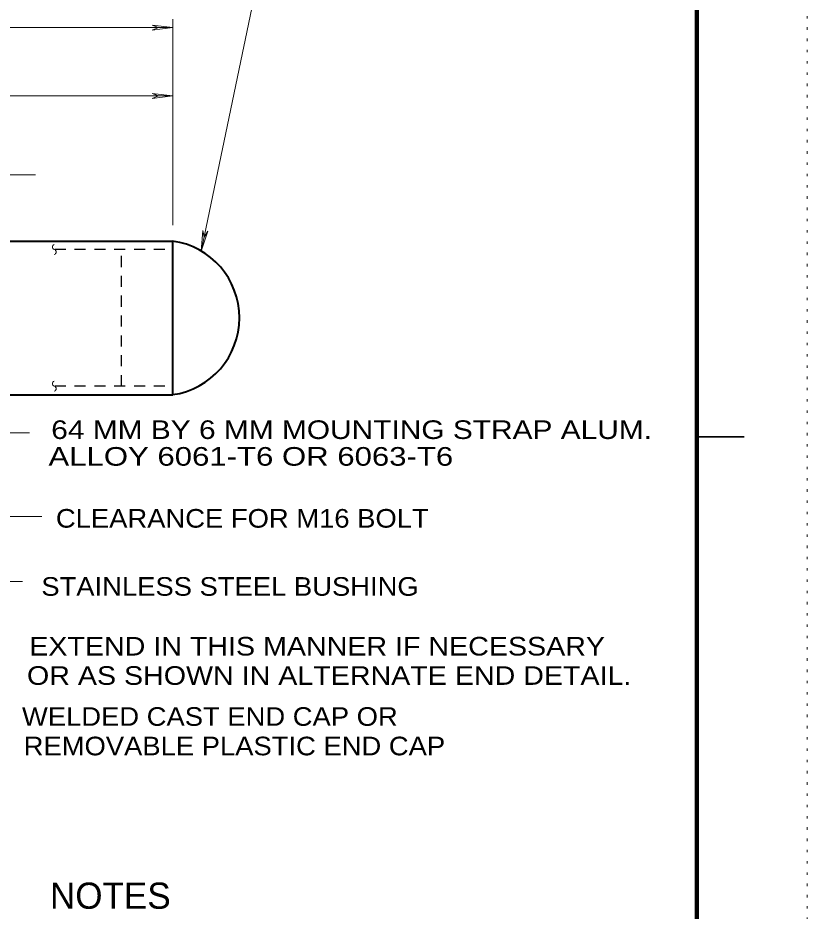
# Model space of a CAD drawing. Extents: x 312583 to 312854, y 144419 to 144597.
# Drawn here: x 312821.27 to 312853.5, y 144484.26 to 144520.73 of the extents above; entities that cross this region are included whole.
import ezdxf
from ezdxf.enums import TextEntityAlignment as Align

# ---------------------------------------------------------------- set-up
doc = ezdxf.new("R2010")
doc.units = 0
doc.header["$LTSCALE"] = 0.3
doc.linetypes.add('DOTTED', pattern=[1.5, 0.3, -1.2])
doc.linetypes.add('SHORT_DASHED', pattern=[2.7, 1.5, -1.2])
for name, color, linetype, lineweight in [('1', 7, 'Continuous', 13), ('2', 7, 'Continuous', 40), ('62', 7, 'DOTTED', 13)]:
    doc.layers.add(name, color=color, linetype=linetype, lineweight=lineweight)

msp = doc.modelspace()

# ---------------------------------------------------------------- linework, layer by layer
at = {"layer": '1'}
for p, q in [((312826.7529, 144520.4346), (312827.0213, 144520.3349)), ((312827.5963, 144520.3349), (312826.7529, 144520.4346)), ((312827.5963, 144512.2619), (312827.5963, 144520.6799)), ((312802.5033, 144520.3349), (312827.5963, 144520.3349)), ((312826.7529, 144520.2276), (312827.0213, 144520.3349)), ((312827.5963, 144520.3349), (312826.7529, 144520.2276)), ((312810.8676, 144517.5442), (312827.5963, 144517.5442)), ((312826.7529, 144517.6439), (312827.0213, 144517.5442)), ((312827.5963, 144517.5442), (312826.7529, 144517.6439)), ((312826.7529, 144517.4446), (312827.0213, 144517.5442)), ((312827.5963, 144517.5442), (312826.7529, 144517.4446)), ((312821.9996, 144514.3166), (312816.4183, 144514.3166)), ((312828.7616, 144511.2116), (312828.8306, 144512.0549)), ((312828.7616, 144511.2116), (312829.0299, 144512.0166)), ((312828.8306, 144512.0549), (312828.8766, 144511.7712)), ((312829.0299, 144512.0166), (312828.8766, 144511.7712)), ((312820.8573, 144500.3786), (312822.2526, 144500.3786))]:
    msp.add_line(p, q, dxfattribs=at)
at = {"layer": '1', "lineweight": 40}
for p, q in [((312814.3483, 144511.6179), (312827.5963, 144511.6179)), ((312827.5963, 144505.3466), (312827.5963, 144511.6179)), ((312814.3483, 144505.3466), (312827.5963, 144505.3466))]:
    msp.add_line(p, q, dxfattribs=at)
at = {"layer": '1', "linetype": 'SHORT_DASHED', "lineweight": 25}
for p, q in [((312827.2819, 144511.2729), (312822.7586, 144511.2729)), ((312825.5033, 144505.6992), (312825.5033, 144511.2729)), ((312827.2819, 144505.6992), (312822.7586, 144505.6992))]:
    msp.add_line(p, q, dxfattribs=at)
at = {"layer": '1', "lineweight": 35}
msp.add_line((312849, 144503.6216), (312850.932, 144503.6216), dxfattribs=at)
at = {"layer": '1', "lineweight": 158}
msp.add_lwpolyline([(312616.5, 144423.0846), (312849, 144423.0846), (312849, 144585.0846)], dxfattribs=at)
at = {"layer": '1'}
for points in [[(312828.7616, 144511.2116), (312831.3759, 144523.7542), (312829.9806, 144523.7542)], [(312814.3483, 144502.9086), (312820.3589, 144503.7902), (312821.7543, 144503.7902)], [(312811.8413, 144501.0992), (312820.0753, 144497.7259), (312821.4629, 144497.7259)]]:
    msp.add_lwpolyline(points, dxfattribs=at)
at = {"layer": '1', "lineweight": 40}
msp.add_arc((312827.1508, 144508.4836), 3.1675, 278.04577, 81.95422, dxfattribs=at)
at = {"layer": '1'}
for centre, start, end in [((312822.787, 144511.3724), 105, 255), ((312822.7329, 144511.1706), 285, 75), ((312822.787, 144505.7967), 105, 255), ((312822.7329, 144505.5948), 285, 75)]:
    msp.add_arc(centre, 0.1045, start, end, dxfattribs=at)
at = {"layer": '62'}
msp.add_lwpolyline([(312601.2, 144418.5846), (312853.5, 144418.5846), (312853.5, 144596.7846)], dxfattribs=at)

# ---------------------------------------------------------------- texts
at = {"layer": '1'}
for s, width, p in [('64 MM BY 6 MM MOUNTING STRAP ALUM.', 1.2, (312822.6373, 144503.5377)), ('ALLOY 6061-T6 OR 6063-T6', 1.25, (312822.525, 144502.4471)), ('CLEARANCE FOR M16 BOLT', 1.1, (312822.8283, 144499.9181)), ('STAINLESS STEEL BUSHING', 1.1, (312822.2322, 144497.137)), ('EXTEND IN THIS MANNER IF NECESSARY', 1.15, (312821.7392, 144494.6971)), ('OR AS SHOWN IN ALTERNATE END DETAIL.', 1.15, (312821.6469, 144493.5005)), ('WELDED CAST END CAP OR', 1.1, (312821.4418, 144491.8278)), ('REMOVABLE PLASTIC END CAP', 1.1, (312821.5123, 144490.6232))]:
    msp.add_text(s, height=0.76, dxfattribs=dict(at, width=width)).set_placement(p)
at = {"layer": '2'}
msp.add_text('NOTES', height=1.07, dxfattribs=at).set_placement((312825.0505, 144484.3583), align=Align.CENTER)

doc.saveas('drawing.dxf')
